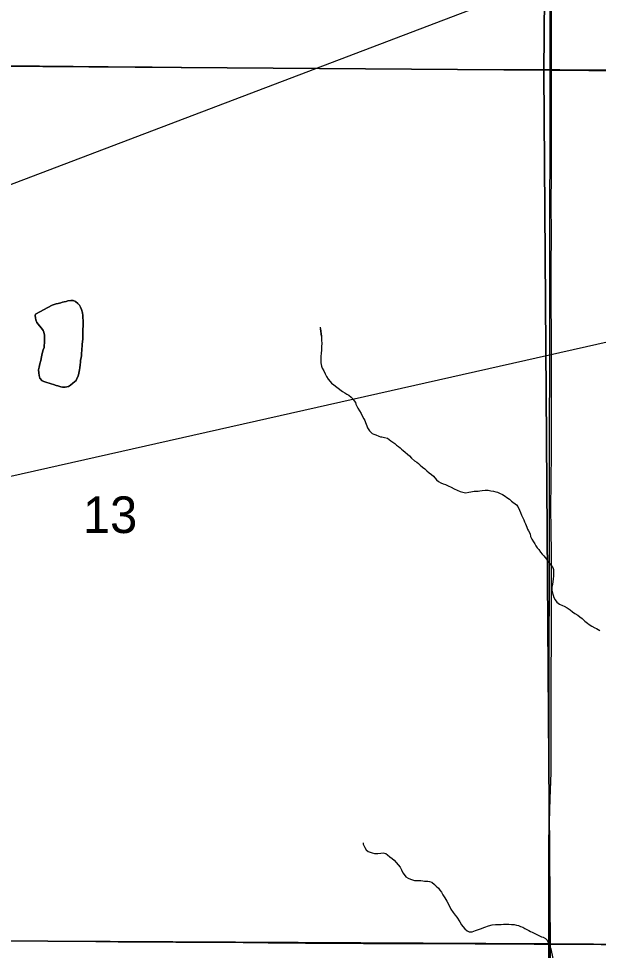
# Model space of a CAD drawing. Extents: x -17 to 88, y -5 to 22.
# Drawn here: x 8.123 to 8.787, y 17.134 to 18.199 of the extents above; entities that cross this region are included whole.
import ezdxf

# ---------------------------------------------------------------- set-up
doc = ezdxf.new("R2010")
doc.units = 0
for name, color, linetype in [('GM_X_County_Road', 7, 'Continuous'), ('GM_X_Minor_Lake', 7, 'Continuous'), ('GM_X_Minor_River', 7, 'Continuous'), ('GM_X_Section', 7, 'Continuous'), ('GM_X_Section_Text', 7, 'Continuous'), ('GM_X_Township', 7, 'Continuous'), ('GM_X_Township_Road', 7, 'Continuous'), ('TX_P_10', 7, 'Continuous')]:
    doc.layers.add(name, color=color, linetype=linetype)

msp = doc.modelspace()

# ---------------------------------------------------------------- linework, layer by layer
at = {"layer": 'GM_X_County_Road'}
for points in [[(8.733, 18.1413), (8.7329, 18.1995), (8.7329, 18.2468), (8.733, 18.2834), (8.7331, 18.3338), (8.7331, 18.3692), (8.7333, 18.4114), (8.7335, 18.4661), (8.7337, 18.5134), (8.7337, 18.583), (8.7338, 18.6588), (8.734, 18.765), (8.734, 18.8744), (8.7343, 18.9558), (8.7343, 19.0435), (8.7348, 19.1441)], [(8.7317, 17.1409), (8.7308, 17.2807), (8.7317, 17.3074), (8.7325, 17.3366), (8.7326, 17.4205), (8.7328, 17.454), (8.7331, 17.4844), (8.7331, 17.5124), (8.733, 17.544), (8.7329, 17.5695), (8.733, 17.59), (8.7328, 17.6124), (8.7324, 17.6422), (8.7327, 17.6671), (8.7332, 17.7062), (8.7331, 17.7658), (8.7329, 17.841), (8.7328, 17.8714), (8.7328, 17.9043), (8.7329, 17.9634), (8.7328, 17.9771), (8.733, 18.0317), (8.733, 18.1281), (8.733, 18.1413)], [(8.733, 18.1413), (8.7426, 18.1412), (8.7649, 18.1408), (8.8153, 18.1406), (8.87, 18.1403), (8.9638, 18.1398), (9.0496, 18.1391), (9.0881, 18.1389), (9.1161, 18.1388), (9.177, 18.1384), (9.2161, 18.1381), (9.2727, 18.1378), (9.3224, 18.1377), (9.4, 18.1373)], [(7.9812, 17.1456), (7.9937, 17.1455), (8.0111, 17.1454), (8.1055, 17.1445), (8.2118, 17.1439), (8.2373, 17.1436), (8.3031, 17.1432), (8.3224, 17.1432), (8.3802, 17.1427), (8.4088, 17.1424), (8.4516, 17.142), (8.5181, 17.1416), (8.548, 17.1416), (8.6145, 17.1414), (8.6456, 17.1411), (8.7133, 17.1409), (8.7317, 17.1409)], [(8.7317, 17.1409), (8.7586, 17.1408), (8.7897, 17.1404), (8.8145, 17.1403), (8.8772, 17.1401), (8.9107, 17.1401), (8.9691, 17.1399), (9.0151, 17.1397), (9.0661, 17.1396), (9.0859, 17.1396), (9.125, 17.1398), (9.1884, 17.14), (9.2362, 17.1399), (9.2857, 17.1397), (9.2925, 17.1398), (9.3167, 17.1398), (9.3795, 17.1401), (9.4, 17.1402)], [(8.7319, 17.1317), (8.7317, 17.1409)]]:
    msp.add_lwpolyline(points, dxfattribs=at)
at = {"layer": 'GM_X_Minor_Lake'}
for points in [[(8.1428, 17.8613), (8.1617, 17.8716), (8.164, 17.8723), (8.1663, 17.873), (8.1686, 17.8737), (8.1716, 17.8744), (8.1735, 17.8751), (8.1754, 17.8755), (8.1777, 17.8758), (8.1796, 17.8765), (8.1831, 17.8769), (8.1857, 17.8768), (8.1884, 17.876), (8.191, 17.8737), (8.1928, 17.8717), (8.1943, 17.8694), (8.1954, 17.8668), (8.1965, 17.8629), (8.1968, 17.8599), (8.1968, 17.8572), (8.1971, 17.8542), (8.197, 17.8508), (8.197, 17.8474), (8.1969, 17.8447), (8.1969, 17.8428), (8.1968, 17.8405), (8.1968, 17.8379), (8.1967, 17.8356), (8.1967, 17.8333), (8.1966, 17.8295), (8.1962, 17.8269), (8.1961, 17.8242), (8.1957, 17.8219), (8.1957, 17.8197), (8.1952, 17.8166), (8.1952, 17.814), (8.1948, 17.8113), (8.1943, 17.8087), (8.1943, 17.8064), (8.1939, 17.8034), (8.1934, 17.8), (8.193, 17.7977), (8.1926, 17.7958), (8.1922, 17.7939), (8.1913, 17.7905), (8.1901, 17.7879), (8.189, 17.7856), (8.1855, 17.7823), (8.1828, 17.78), (8.1805, 17.7786), (8.1766, 17.7779), (8.1736, 17.7779), (8.1717, 17.7783), (8.1683, 17.7792), (8.1664, 17.7796), (8.1634, 17.7808), (8.1607, 17.7816), (8.1581, 17.7824), (8.1558, 17.7832), (8.1532, 17.784), (8.1502, 17.7852), (8.1476, 17.7883), (8.1469, 17.7913), (8.1465, 17.7944), (8.1462, 17.7978), (8.1467, 17.8008), (8.1475, 17.8046), (8.1487, 17.8084), (8.1495, 17.8125), (8.1504, 17.8163), (8.1516, 17.8205), (8.1524, 17.8231), (8.1524, 17.8254), (8.1529, 17.8284), (8.153, 17.8326), (8.153, 17.8349), (8.153, 17.8372), (8.1523, 17.8406), (8.1516, 17.8425), (8.1494, 17.8452), (8.1472, 17.8479), (8.1442, 17.8518), (8.1431, 17.8548), (8.1428, 17.8571), (8.1424, 17.8598), (8.1428, 17.8613)], [(8.1926, 17.7958), (8.193, 17.7977), (8.1934, 17.8), (8.1939, 17.8034), (8.1943, 17.8064), (8.1943, 17.8087), (8.1948, 17.8113), (8.1952, 17.814), (8.1952, 17.8166), (8.1957, 17.8197), (8.1957, 17.8219), (8.1961, 17.8242), (8.1962, 17.8269), (8.1966, 17.8295), (8.1967, 17.8333), (8.1967, 17.8356), (8.1968, 17.8379), (8.1968, 17.8405), (8.1969, 17.8428), (8.1969, 17.8447), (8.197, 17.8474), (8.197, 17.8508), (8.1971, 17.8542), (8.1968, 17.8572), (8.1968, 17.8599), (8.1965, 17.8629), (8.1954, 17.8668), (8.1943, 17.8694), (8.1928, 17.8717), (8.191, 17.8737), (8.1884, 17.876), (8.1857, 17.8768), (8.1831, 17.8769), (8.1796, 17.8765), (8.1777, 17.8758), (8.1754, 17.8755), (8.1735, 17.8751), (8.1716, 17.8744), (8.1686, 17.8737), (8.1663, 17.873), (8.164, 17.8723), (8.1617, 17.8716), (8.1428, 17.8613)], [(8.1428, 17.8613), (8.1424, 17.8598), (8.1428, 17.8571), (8.1431, 17.8548), (8.1442, 17.8518), (8.1472, 17.8479), (8.1494, 17.8452), (8.1516, 17.8425), (8.1523, 17.8406), (8.153, 17.8372), (8.153, 17.8349), (8.153, 17.8326), (8.1529, 17.8284), (8.1524, 17.8254), (8.1524, 17.8231), (8.1516, 17.8205), (8.1504, 17.8163), (8.1495, 17.8125), (8.1487, 17.8084), (8.1475, 17.8046), (8.1467, 17.8008), (8.1462, 17.7978), (8.1465, 17.7944), (8.1469, 17.7913), (8.1476, 17.7883), (8.1502, 17.7852), (8.1532, 17.784), (8.1558, 17.7832), (8.1581, 17.7824), (8.1607, 17.7816), (8.1634, 17.7808), (8.1664, 17.7796), (8.1683, 17.7792), (8.1717, 17.7783), (8.1736, 17.7779), (8.1766, 17.7779), (8.1805, 17.7786), (8.1828, 17.78), (8.1855, 17.7823), (8.189, 17.7856), (8.1901, 17.7879), (8.1913, 17.7905), (8.1922, 17.7939), (8.1926, 17.7958)]]:
    msp.add_lwpolyline(points, dxfattribs=at)
at = {"layer": 'GM_X_Minor_River'}
for points in [[(8.4684, 17.8465), (8.4697, 17.8362), (8.4688, 17.8446), (8.4697, 17.8362), (8.47, 17.8317), (8.4703, 17.8278), (8.4699, 17.8244), (8.4698, 17.8206), (8.4694, 17.8165), (8.4693, 17.8131), (8.4693, 17.81), (8.4692, 17.8081), (8.4692, 17.8058), (8.4695, 17.8039), (8.4699, 17.802), (8.4706, 17.7997), (8.4724, 17.7967), (8.4739, 17.7932), (8.4757, 17.7902), (8.4776, 17.7871), (8.4798, 17.7844), (8.4813, 17.7825), (8.4839, 17.7805), (8.4922, 17.7739), (8.494, 17.7727), (8.4967, 17.7712), (8.4989, 17.77), (8.5012, 17.7688), (8.5038, 17.7665), (8.506, 17.7641), (8.5071, 17.7622), (8.5086, 17.7603), (8.5093, 17.7584), (8.5104, 17.7561), (8.5115, 17.7538), (8.5134, 17.7507), (8.5152, 17.7476), (8.5167, 17.7442), (8.5185, 17.7415), (8.5196, 17.7396), (8.5204, 17.7373), (8.5211, 17.7354), (8.5218, 17.7335), (8.5225, 17.7312), (8.5247, 17.7277), (8.5277, 17.725), (8.5296, 17.7242), (8.5319, 17.7234), (8.5353, 17.7218), (8.5372, 17.721), (8.5391, 17.721), (8.5421, 17.7202), (8.5455, 17.7194), (8.5493, 17.7166), (8.5515, 17.7151), (8.5538, 17.7135), (8.5556, 17.7116), (8.5579, 17.71), (8.5597, 17.7085), (8.5616, 17.7069), (8.5635, 17.7054), (8.5706, 17.6992), (8.5728, 17.6965), (8.5762, 17.6937), (8.5788, 17.6922), (8.5807, 17.6906), (8.5829, 17.6887), (8.5856, 17.6863), (8.5882, 17.6844), (8.5904, 17.6821), (8.593, 17.6797), (8.5957, 17.6778), (8.5979, 17.6759), (8.6013, 17.672), (8.6039, 17.6701), (8.6065, 17.6685), (8.6092, 17.6673), (8.6118, 17.6665), (8.6148, 17.6649), (8.6182, 17.6633), (8.6216, 17.6617), (8.625, 17.6602), (8.6284, 17.6586), (8.6314, 17.6578), (8.6333, 17.6574), (8.6352, 17.6569), (8.6386, 17.6576), (8.6409, 17.658), (8.6447, 17.6587), (8.6474, 17.659), (8.6493, 17.659), (8.6512, 17.6593), (8.6539, 17.6596), (8.6573, 17.6599), (8.6604, 17.6599), (8.6638, 17.6594), (8.6668, 17.659), (8.6695, 17.6582), (8.6713, 17.6578), (8.6736, 17.6566), (8.677, 17.655)], [(8.677, 17.655), (8.68, 17.6531), (8.6819, 17.6515), (8.6849, 17.6499), (8.6871, 17.6476), (8.6931, 17.6433), (8.6946, 17.6414), (8.6964, 17.6372), (8.6975, 17.6345), (8.6986, 17.6315), (8.7001, 17.6284), (8.7015, 17.6261), (8.7023, 17.6238), (8.7034, 17.6215), (8.7041, 17.6196), (8.7048, 17.6177), (8.7055, 17.6154), (8.7066, 17.6135), (8.7085, 17.61), (8.7092, 17.607), (8.7106, 17.6039), (8.7125, 17.6008), (8.714, 17.5985), (8.7151, 17.5962), (8.7165, 17.5939), (8.7184, 17.592), (8.7203, 17.5893), (8.7225, 17.587), (8.7244, 17.585), (8.7258, 17.5831), (8.7273, 17.5812), (8.7295, 17.5777), (8.7321, 17.5743), (8.7344, 17.5716), (8.7355, 17.5693), (8.7354, 17.567), (8.7354, 17.5647), (8.7353, 17.5617), (8.7349, 17.5586), (8.734, 17.5522), (8.7336, 17.5492), (8.7335, 17.5461), (8.7339, 17.5438), (8.7349, 17.54), (8.7356, 17.5374), (8.7371, 17.5347), (8.7393, 17.532), (8.7423, 17.5296), (8.7457, 17.5281), (8.7476, 17.5273), (8.751, 17.5253), (8.7544, 17.523), (8.757, 17.521), (8.7596, 17.5191), (8.763, 17.5171), (8.7656, 17.5152), (8.7683, 17.5132), (8.7712, 17.5101), (8.7742, 17.5078), (8.7761, 17.5062), (8.7791, 17.5043), (8.7825, 17.5027), (8.7844, 17.5019), (8.7863, 17.5007), (8.7885, 17.4995)], [(8.5175, 17.2566), (8.5174, 17.2551), (8.5193, 17.2512), (8.5211, 17.2486), (8.5234, 17.2466), (8.5256, 17.2458), (8.5279, 17.2454), (8.5306, 17.2446), (8.5344, 17.2445), (8.5378, 17.2448), (8.5404, 17.2452), (8.5435, 17.2443), (8.5453, 17.2428), (8.548, 17.2408), (8.5506, 17.2389), (8.5532, 17.2369), (8.5555, 17.2342), (8.5577, 17.2315), (8.5599, 17.2288), (8.5614, 17.2258), (8.5628, 17.2223), (8.5643, 17.2204), (8.5665, 17.2177), (8.5692, 17.2161), (8.5718, 17.215), (8.5741, 17.2142), (8.5764, 17.2137), (8.579, 17.2137), (8.5813, 17.2136), (8.5836, 17.2136), (8.5859, 17.2132), (8.5877, 17.2128), (8.5897, 17.2127), (8.5915, 17.2127), (8.5934, 17.2123), (8.5961, 17.2118), (8.5991, 17.2091), (8.601, 17.2072), (8.6036, 17.2049), (8.6054, 17.2026), (8.6073, 17.2002), (8.6088, 17.1972), (8.611, 17.1937), (8.6132, 17.1899), (8.615, 17.1864), (8.6179, 17.1807), (8.6205, 17.1768), (8.6228, 17.1741), (8.6246, 17.1718), (8.6283, 17.1664), (8.6302, 17.163), (8.6317, 17.1611), (8.6339, 17.1584), (8.6365, 17.156), (8.6388, 17.1549), (8.6422, 17.1548), (8.646, 17.1562), (8.6518, 17.1584), (8.6567, 17.1602), (8.6609, 17.1617), (8.6651, 17.1627), (8.669, 17.1634), (8.6712, 17.1634), (8.6731, 17.1633), (8.6754, 17.1633), (8.6781, 17.1636), (8.6811, 17.1636), (8.6842, 17.1635), (8.6872, 17.1634), (8.6902, 17.1634), (8.6929, 17.1626), (8.6952, 17.1622), (8.6974, 17.161), (8.7001, 17.1602), (8.7027, 17.1586), (8.705, 17.1574), (8.7072, 17.1562), (8.7091, 17.1551), (8.711, 17.1546), (8.714, 17.1531), (8.7163, 17.1519), (8.7185, 17.1507), (8.7215, 17.1491), (8.7234, 17.1487), (8.7261, 17.1472), (8.7279, 17.1452), (8.7301, 17.141), (8.7312, 17.1383), (8.7323, 17.1353), (8.7344, 17.1242)]]:
    msp.add_lwpolyline(points, dxfattribs=at)
at = {"layer": 'GM_X_Section'}
for points in [[(8.7326, 19.1414), (8.7311, 18.1404), (7.729, 18.1476), (7.7351, 19.1493)], [(8.7311, 18.1404), (8.7296, 17.1413), (7.7267, 17.1466), (7.729, 18.1476)], [(7.7267, 17.1466), (8.7296, 17.1413), (8.7243, 16.1407), (7.7116, 16.1511)]]:
    msp.add_lwpolyline(points, close=True, dxfattribs=at)
for points in [[(9.4, 19.1346), (8.7326, 19.1414), (8.7311, 18.1404), (9.4, 18.1346)], [(9.4, 18.1346), (8.7311, 18.1404), (8.7296, 17.1413), (9.4, 17.136)], [(9.4, 17.136), (8.7296, 17.1413), (8.7243, 16.1407), (9.4, 16.1356)]]:
    msp.add_lwpolyline(points, dxfattribs=at)
at = {"layer": 'GM_X_Township'}
for points in [[(9.4, 20.1669), (8.7281, 20.1646), (8.7274, 19.89), (8.7348, 19.4138), (8.7331, 19.1436), (8.7241, 18.1383), (8.7317, 17.1395), (8.7273, 16.2993), (8.7261, 16.1499), (8.7243, 15.8906), (8.7164, 14.7728), (8.709, 14.1)], [(8.709, 14.1), (8.7164, 14.7728), (8.7243, 15.8906), (8.7261, 16.1499), (8.7273, 16.2993), (8.7317, 17.1395), (8.7241, 18.1383), (8.7331, 19.1436), (8.236, 19.1446), (7.7361, 19.149), (7.2261, 19.1535), (6.9691, 19.1558), (6.2534, 19.1527), (5.7225, 19.1491), (5.7215, 18.6472), (5.7149, 18.1469), (5.0464, 18.1513)]]:
    msp.add_lwpolyline(points, dxfattribs=at)
at = {"layer": 'GM_X_Township_Road'}
msp.add_lwpolyline([(7.7311, 18.1473), (7.7503, 18.1471), (7.7987, 18.1471), (7.9324, 18.1466), (7.9982, 18.1461), (8.0628, 18.1461), (8.0778, 18.1461), (8.0883, 18.146), (8.1088, 18.1457), (8.1859, 18.1451), (8.2256, 18.1445), (8.276, 18.1442), (8.3437, 18.1436), (8.3723, 18.1432), (8.4021, 18.143), (8.4879, 18.1422), (8.5488, 18.1419), (8.5886, 18.1415), (8.6687, 18.141), (8.7072, 18.1413), (8.7239, 18.1413), (8.733, 18.1413)], dxfattribs=at)
at = {"layer": 'TX_P_10'}
msp.add_lwpolyline([(5.9567, 17.1898), (9.6824, 18.6059), (9.6824, 18.0286)], close=True, dxfattribs=at)

# ---------------------------------------------------------------- texts
at = {"layer": 'GM_X_Section_Text'}
msp.add_text('13', height=0.04186, rotation=0, dxfattribs=at).set_placement((8.1968, 17.611))

doc.saveas('drawing.dxf')
